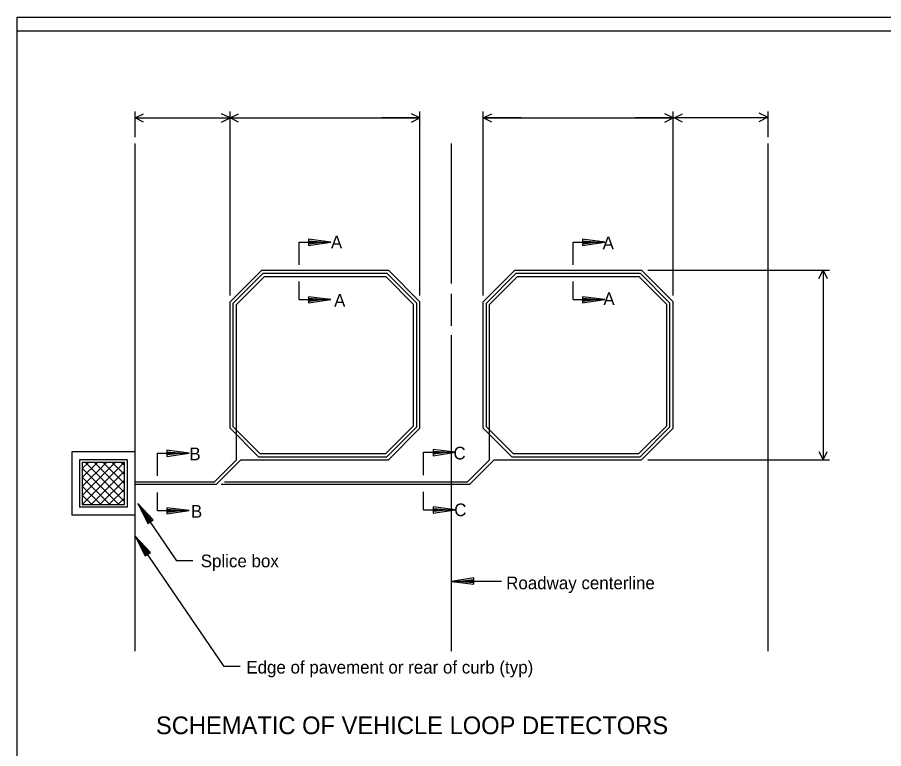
# Model space of a CAD drawing. Extents: x 0 to 390, y 0 to 265.
# Drawn here: x 0 to 160.8, y 129.2 to 265 of the extents above; entities that cross this region are included whole.
import ezdxf

# ---------------------------------------------------------------- set-up
doc = ezdxf.new("R2010")
doc.units = 0
doc.layers.add('D_Details', color=7, linetype='Continuous')
doc.layers.add('Default', color=7, linetype='Continuous')

msp = doc.modelspace()

# ---------------------------------------------------------------- linework, layer by layer
at = {"layer": 'D_Details'}
for p, q in [((21.87, 242.74), (21.87, 247.5)), ((21.87, 246.33), (39.49, 246.33)), ((39.49, 213.37), (39.49, 247.5)), ((39.49, 246.33), (74.73, 246.33)), ((74.73, 246.33), (67.68, 246.33)), ((74.73, 213.37), (74.73, 247.5)), ((86.48, 213.37), (86.48, 247.5)), ((93.52, 246.33), (86.48, 246.33)), ((86.48, 246.33), (121.72, 246.33)), ((121.72, 246.33), (114.67, 246.33)), ((121.72, 213.37), (121.72, 247.5)), ((139.33, 246.33), (121.72, 246.33)), ((139.33, 242.74), (139.33, 247.5)), ((21.87, 147.36), (21.87, 241.57)), ((80.6, 215.57), (80.6, 241.57)), ((139.33, 147.36), (139.33, 241.57)), ((58.17, 223.28), (54.06, 223.81)), ((54.06, 223.81), (54.06, 222.63)), ((54.06, 223.51), (57.14, 223.28)), ((109.03, 223.28), (104.92, 223.81)), ((104.92, 223.81), (104.92, 222.63)), ((104.92, 223.51), (108, 223.28)), ((52.29, 223.28), (58.17, 223.28)), ((52.29, 219.04), (52.29, 223.28)), ((54.06, 223.36), (55.53, 223.25)), ((54.06, 222.63), (58.17, 223.28)), ((57.14, 223.28), (54.06, 222.92)), ((55.53, 223.25), (54.06, 223.07)), ((103.16, 223.28), (109.03, 223.28)), ((103.16, 219.04), (103.16, 223.28)), ((104.92, 223.36), (106.39, 223.25)), ((104.92, 222.63), (109.03, 223.28)), ((108, 223.28), (104.92, 222.92)), ((106.39, 223.25), (104.92, 223.07)), ((45.36, 218.07), (39.49, 212.2)), ((45.61, 217.49), (40.08, 211.95)), ((45.36, 218.07), (68.86, 218.07)), ((45.61, 217.49), (68.61, 217.49)), ((68.61, 217.49), (74.14, 211.95)), ((68.86, 218.07), (74.73, 212.2)), ((92.35, 218.07), (86.48, 212.2)), ((92.6, 217.49), (87.06, 211.95)), ((92.35, 218.07), (115.84, 218.07)), ((92.6, 217.49), (115.6, 217.49)), ((115.6, 217.49), (121.13, 211.95)), ((115.84, 218.07), (121.72, 212.2)), ((117.02, 218.07), (150.72, 218.07)), ((149.55, 218.07), (149.55, 182.83)), ((45.85, 216.9), (40.67, 211.72)), ((45.85, 216.9), (68.38, 216.9)), ((52.29, 212.61), (52.29, 215.96)), ((68.38, 216.9), (73.56, 211.72)), ((92.83, 216.9), (87.65, 211.72)), ((92.83, 216.9), (115.36, 216.9)), ((103.16, 212.61), (103.16, 215.96)), ((115.36, 216.9), (120.54, 211.72)), ((52.29, 212.61), (58.17, 212.61)), ((58.17, 212.61), (54.06, 213.14)), ((54.06, 213.14), (54.06, 211.97)), ((54.06, 212.85), (57.14, 212.61)), ((54.06, 212.7), (55.53, 212.58)), ((54.06, 211.97), (58.17, 212.61)), ((57.14, 212.61), (54.06, 212.26)), ((55.53, 212.58), (54.06, 212.41)), ((80.6, 207.72), (80.6, 213.65)), ((103.16, 212.61), (109.03, 212.61)), ((109.03, 212.61), (104.92, 213.14)), ((104.92, 213.14), (104.92, 211.97)), ((104.92, 212.85), (108, 212.61)), ((104.92, 212.7), (106.39, 212.58)), ((104.92, 211.97), (109.03, 212.61)), ((108, 212.61), (104.92, 212.26)), ((106.39, 212.58), (104.92, 212.41)), ((39.49, 188.71), (39.49, 212.2)), ((40.08, 188.95), (40.08, 211.95)), ((40.67, 182.83), (40.67, 211.72)), ((73.56, 189.19), (73.56, 211.72)), ((74.14, 188.95), (74.14, 211.95)), ((74.73, 188.71), (74.73, 212.2)), ((86.48, 188.71), (86.48, 212.2)), ((87.06, 188.95), (87.06, 211.95)), ((87.65, 182.83), (87.65, 211.72)), ((120.54, 189.19), (120.54, 211.72)), ((121.13, 188.95), (121.13, 211.95)), ((121.72, 188.71), (121.72, 212.2)), ((80.6, 147.36), (80.6, 205.98)), ((39.49, 188.71), (44.78, 183.42)), ((40.08, 188.95), (45.02, 184.01)), ((73.56, 189.19), (68.38, 184.01)), ((74.14, 188.95), (68.61, 183.42)), ((74.73, 188.71), (68.86, 182.83)), ((86.48, 188.71), (91.76, 183.42)), ((87.06, 188.95), (92.01, 184.01)), ((120.54, 189.19), (115.36, 184.01)), ((121.13, 188.95), (115.6, 183.42)), ((121.72, 188.71), (115.84, 182.83)), ((21.84, 184.33), (10.1, 184.33)), ((10.1, 184.33), (10.1, 172.59)), ((21.84, 184.33), (21.84, 172.59)), ((26, 184.11), (31.87, 184.11)), ((26, 179.87), (26, 184.11)), ((31.87, 184.11), (27.76, 184.64)), ((27.76, 184.64), (27.76, 183.46)), ((27.76, 184.34), (30.84, 184.11)), ((27.76, 184.2), (29.23, 184.08)), ((27.76, 183.46), (31.87, 184.11)), ((30.84, 184.11), (27.76, 183.76)), ((29.23, 184.08), (27.76, 183.9)), ((44.78, 183.42), (68.61, 183.42)), ((45.02, 184.01), (68.38, 184.01)), ((75.39, 184.26), (81.26, 184.26)), ((75.39, 180.02), (75.39, 184.26)), ((81.26, 184.26), (77.15, 184.78)), ((77.15, 184.78), (77.15, 183.61)), ((77.15, 184.49), (80.23, 184.26)), ((77.15, 184.34), (78.62, 184.23)), ((77.15, 183.61), (81.26, 184.26)), ((80.23, 184.26), (77.15, 183.9)), ((78.62, 184.23), (77.15, 184.05)), ((91.76, 183.42), (115.6, 183.42)), ((92.01, 184.01), (115.36, 184.01)), ((11.56, 182.86), (11.56, 174.05)), ((20.37, 182.86), (11.56, 182.86)), ((20.37, 182.86), (20.37, 174.05)), ((36.51, 178.68), (40.67, 182.83)), ((36.93, 178.27), (41.5, 182.83)), ((39.49, 182.83), (39.49, 182.83)), ((41.5, 182.83), (68.86, 182.83)), ((83.5, 178.68), (87.65, 182.83)), ((83.92, 178.27), (88.48, 182.83)), ((86.48, 182.83), (86.48, 182.83)), ((86.48, 182.83), (86.48, 182.83)), ((88.48, 182.83), (115.84, 182.83)), ((117.02, 182.83), (150.72, 182.83)), ((36.51, 178.68), (21.87, 178.68)), ((83.5, 178.68), (38.44, 178.68)), ((36.93, 178.27), (21.88, 178.27)), ((83.92, 178.27), (37.82, 178.27)), ((75.39, 173.59), (75.39, 176.94)), ((26, 173.44), (26, 176.8)), ((20.37, 174.05), (11.56, 174.05)), ((29.63, 164.08), (22.34, 174.75)), ((22.34, 174.75), (24.22, 171.05)), ((25.2, 171.72), (22.34, 174.75)), ((24.47, 171.22), (22.92, 173.9)), ((22.92, 173.9), (24.95, 171.55)), ((31.87, 173.44), (27.76, 173.97)), ((27.76, 173.97), (27.76, 172.8)), ((31.87, 173.44), (27.76, 173.97)), ((27.76, 173.97), (27.76, 172.8)), ((27.76, 173.68), (30.84, 173.44)), ((27.76, 173.68), (30.84, 173.44)), ((81.26, 173.59), (77.15, 174.12)), ((77.15, 174.12), (77.15, 172.94)), ((77.15, 173.83), (80.23, 173.59)), ((77.15, 173.68), (78.62, 173.56)), ((21.84, 172.59), (10.1, 172.59)), ((24.59, 171.3), (23.86, 172.58)), ((23.86, 172.58), (24.83, 171.47)), ((26, 173.44), (31.87, 173.44)), ((27.76, 173.53), (29.23, 173.41)), ((27.76, 173.53), (29.23, 173.41)), ((27.76, 172.8), (31.87, 173.44)), ((30.84, 173.44), (27.76, 173.09)), ((27.76, 172.8), (31.87, 173.44)), ((30.84, 173.44), (27.76, 173.09)), ((29.23, 173.41), (27.76, 173.24)), ((29.23, 173.41), (27.76, 173.24)), ((75.39, 173.59), (81.26, 173.59)), ((77.15, 172.94), (81.26, 173.59)), ((80.23, 173.59), (77.15, 173.24)), ((78.62, 173.56), (77.15, 173.38)), ((24.22, 171.05), (25.2, 171.72)), ((38.4, 144.49), (21.87, 168.7)), ((21.87, 168.7), (23.75, 165.01)), ((24.73, 165.67), (21.87, 168.7)), ((24, 165.17), (22.45, 167.85)), ((22.45, 167.85), (24.48, 165.51)), ((24.12, 165.26), (23.39, 166.54)), ((23.39, 166.54), (24.36, 165.43)), ((23.75, 165.01), (24.73, 165.67)), ((32.57, 164.08), (29.63, 164.08)), ((84.71, 160.92), (80.6, 160.28)), ((84.71, 159.75), (84.71, 160.92)), ((89.86, 160.28), (80.6, 160.28)), ((80.6, 160.28), (84.71, 159.75)), ((81.63, 160.28), (84.71, 160.63)), ((84.71, 160.04), (81.63, 160.28)), ((83.25, 160.31), (84.71, 160.48)), ((84.71, 160.19), (83.25, 160.31)), ((41.34, 144.49), (38.4, 144.49))]:
    msp.add_line(p, q, dxfattribs=at)
for points in [[(23.44, 245.55), (21.87, 246.33), (23.44, 247.11)], [(37.92, 245.55), (39.49, 246.33), (37.92, 247.11)], [(41.06, 245.55), (39.49, 246.33), (41.06, 247.11)], [(73.16, 245.55), (74.73, 246.33), (73.16, 247.11)], [(73.16, 245.55), (74.73, 246.33), (73.16, 247.11)], [(88.04, 245.55), (86.48, 246.33), (88.04, 247.11)], [(88.04, 245.55), (86.48, 246.33), (88.04, 247.11)], [(120.15, 245.55), (121.72, 246.33), (120.15, 247.11)], [(123.48, 245.55), (121.91, 246.33), (123.48, 247.11)], [(137.7, 245.67), (139.26, 246.45), (137.7, 247.23)], [(148.77, 216.5), (149.55, 218.07), (150.33, 216.5)], [(148.77, 184.4), (149.55, 182.83), (150.33, 184.4)], [(12.05, 174.58), (19.85, 182.38)], [(12.05, 176.24), (18.19, 182.38)], [(12.05, 177.9), (16.53, 182.38)], [(12.05, 179.56), (14.87, 182.38)], [(12.05, 181.22), (13.21, 182.38)], [(12.65, 182.38), (19.89, 175.13)], [(14.3, 182.38), (19.89, 176.79)], [(15.96, 182.38), (19.89, 178.45)], [(17.63, 182.38), (19.89, 180.12)], [(19.29, 182.38), (19.88, 181.78)], [(12.05, 181.3), (18.81, 174.54)], [(13.68, 174.54), (19.89, 180.75)], [(12.05, 179.65), (17.16, 174.54)], [(15.34, 174.54), (19.89, 179.09)], [(12.05, 177.98), (15.49, 174.54)], [(17, 174.54), (19.89, 177.43)], [(12.05, 176.32), (13.83, 174.54)], [(18.67, 174.54), (19.89, 175.76)], [(12.05, 174.66), (12.16, 174.55)]]:
    msp.add_lwpolyline(points, dxfattribs=at)
msp.add_lwpolyline([(12.05, 182.38), (12.05, 174.54), (19.89, 174.54), (19.89, 182.38)], close=True, dxfattribs=at)
at = {"layer": 'Default'}
for points in [[(0, 265), (326.25, 265), (326.25, 255), (390, 255), (390, 37.5), (315, 37.5), (315, 0), (0, 0)], [(0, 262.5), (326.25, 262.5), (326.25, 252.5), (390, 252.5), (390, 40), (315, 40), (315, 2.5), (0, 2.5)]]:
    msp.add_lwpolyline(points, close=True, dxfattribs=at)

# ---------------------------------------------------------------- texts
at = {"layer": 'D_Details'}
for s, height, p in [('A', 2.35, (58.21, 222.09)), ('A', 2.35, (108.63, 221.94)), ('A', 2.35, (108.77, 211.57)), ('A', 2.35, (58.79, 211.27)), ('B', 2.35, (31.93, 182.78)), ('C', 2.35, (80.94, 182.93)), ('B', 2.35, (32.22, 172.11)), ('C', 2.35, (81.09, 172.4)), ('Splice box', 2.349, (34.04, 162.91)), ('Roadway centerline', 2.3493, (90.73, 158.83)), ('Edge of pavement or rear of curb (typ)', 2.3493, (42.5, 143.18)), ('SCHEMATIC OF VEHICLE LOOP DETECTORS', 3.2889, (25.73, 131.93))]:
    msp.add_text(s, height=height, dxfattribs=at).set_placement(p)

doc.saveas('drawing.dxf')
